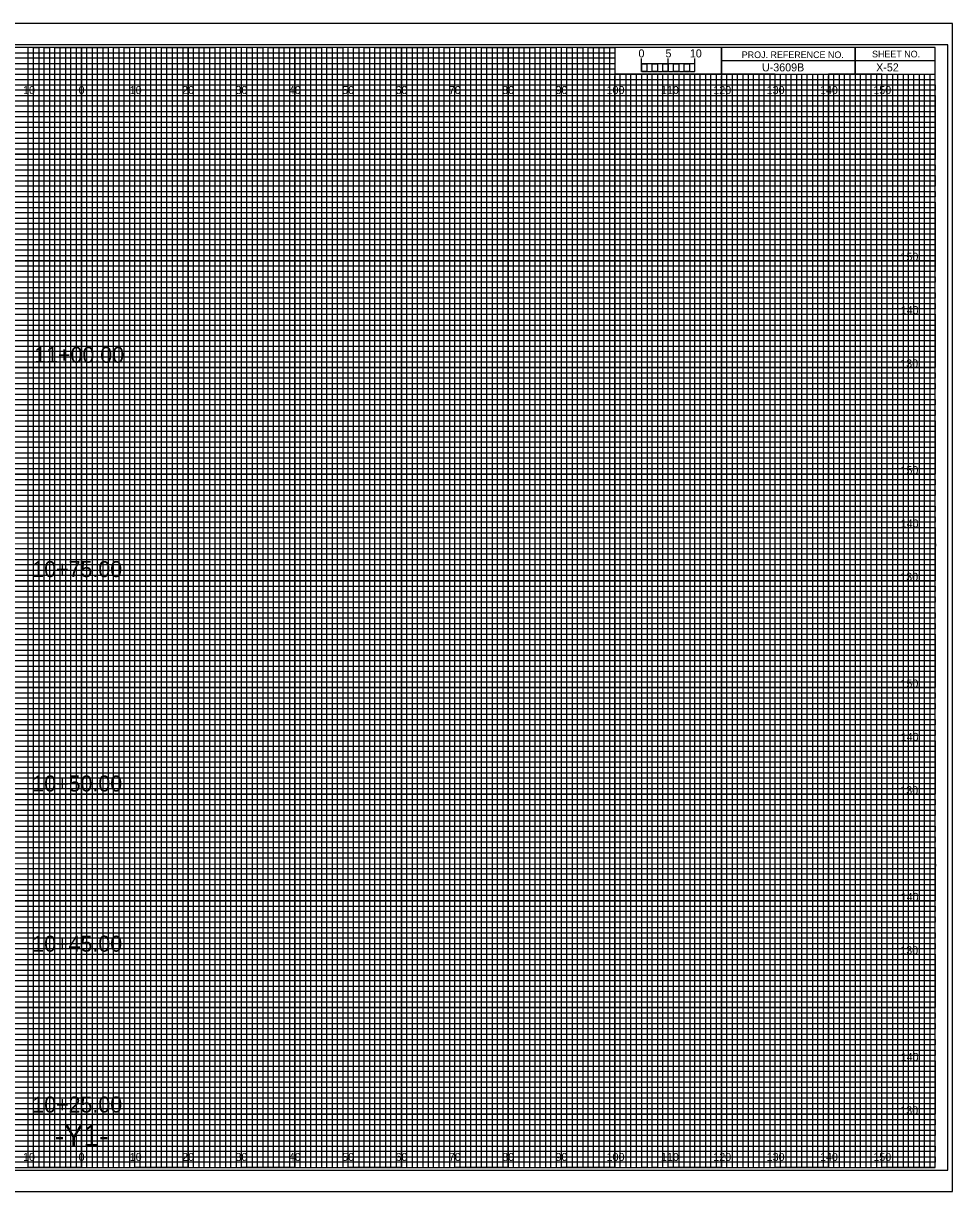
# Model space of a CAD drawing. Extents: x -13 to 323, y -5 to 2634.
# Drawn here: x 149.1 to 323.3, y -4.5 to 214.5 of the extents above; entities that cross this region are included whole.
import ezdxf

# ---------------------------------------------------------------- set-up
doc = ezdxf.new("R2010")
doc.units = 0
for name, color, linetype in [('Exist Cross Section Cell', 7, 'Continuous'), ('Exist XS Center Line Elevation Label', 7, 'Continuous'), ('Exist XS Ground Line', 7, 'Continuous'), ('Prop CMT Pvmt Course 1', 7, 'Continuous'), ('Prop CMT Pvmt Course 1 Wedge', 7, 'Continuous'), ('Prop CMT Pvmt Course 2', 7, 'Continuous'), ('Prop CMT Pvmt Course 2 Wedge', 7, 'Continuous'), ('Prop CMT Pvmt Course 3', 7, 'Continuous'), ('Prop CMT Pvmt Course 3 Wedge', 7, 'Continuous'), ('Prop CMT Pvmt Surface Shoulder', 7, 'Continuous'), ('Prop CMT Pvmt Wedge Surface 3', 7, 'Continuous'), ('Prop CMT Shld Paved Course 1', 7, 'Continuous'), ('Prop CMT Shld Paved Course 2', 7, 'Continuous'), ('Prop CMT Shld Paved Course 3', 7, 'Continuous'), ('Prop CMT Slope Grass', 7, 'Continuous'), ('Prop CMT Subgrade Earthwork', 7, 'Continuous'), ('Scratch_Level_0', 7, 'Continuous')]:
    doc.layers.add(name, color=color, linetype=linetype)

msp = doc.modelspace()

# ---------------------------------------------------------------- linework, layer by layer
at = {"layer": 'Exist XS Center Line Elevation Label'}
for points in [[(145, 0), (155, 0), (155, 210), (165, 210), (165, 0), (175, 0), (175, 210), (185, 210), (185, 0), (195, 0), (195, 210), (205, 210), (205, 0), (215, 0), (215, 210), (225, 210), (225, 0), (235, 0), (235, 210), (245, 210), (245, 0), (255, 0), (255, 210), (259.93, 210), (260, 210), (260, 205), (264.99, 205), (264.99, 0), (275, 0), (275, 205), (285, 205), (285, 0), (295, 0), (295, 205), (305, 205), (305, 0), (315, 0), (315, 205)], [(0, 205), (275, 205)], [(0, 185), (320, 185), (320, 195), (0, 195)], [(0, 165), (320, 165), (320, 175), (0, 175)], [(0, 145), (320, 145), (320, 155), (0, 155)], [(0, 125), (320, 125), (320, 135), (0, 135)], [(0, 105), (320, 105), (320, 115), (0, 115)], [(0, 85), (320, 85), (320, 95), (0, 95)], [(0, 65), (320, 65), (320, 75), (0, 75)], [(0, 45), (320, 45), (320, 55), (0, 55)], [(0, 25), (320, 25), (320, 35), (0, 35)], [(0, 5), (320, 5), (320, 15), (0, 15)]]:
    msp.add_lwpolyline(points, dxfattribs=at)
at = {"layer": 'Exist XS Ground Line'}
for p, q in [((150, 210), (140, 210)), ((150, 0), (150, 210)), ((170, 210), (160, 210)), ((160, 210), (160, 0)), ((170, 0), (170, 210)), ((190, 210), (180, 210)), ((180, 210), (180, 0)), ((190, 0), (190, 210)), ((210, 210), (200, 210)), ((200, 210), (200, 0)), ((210, 0), (210, 210)), ((230, 210), (220, 210)), ((220, 210), (220, 0)), ((230, 0), (230, 210)), ((250, 210), (240, 210)), ((240, 210), (240, 0)), ((250, 0), (250, 210)), ((260, 210), (260, 0)), ((270, 0), (270, 205)), ((290, 205), (280, 205)), ((280, 205), (280, 0)), ((290, 0), (290, 205)), ((310, 205), (300, 205)), ((300, 205), (300, 0)), ((310, 0), (310, 205)), ((160, 0), (150, 0)), ((180, 0), (170, 0)), ((200, 0), (190, 0)), ((220, 0), (210, 0)), ((240, 0), (230, 0)), ((260, 0), (250, 0)), ((280, 0), (270, 0)), ((300, 0), (290, 0)), ((320, 0), (310, 0)), ((320, 0), (320, 0))]:
    msp.add_line(p, q, dxfattribs=at)
for points in [[(0, 200), (320, 200), (320, 190), (0, 190)], [(0, 180), (320, 180), (320, 170), (0, 170)], [(0, 160), (320, 160), (320, 150), (0, 150)], [(0, 140), (320, 140), (320, 130), (0, 130)], [(0, 120), (320, 120), (320, 110), (0, 110)], [(0, 100), (320, 100), (320, 90), (0, 90)], [(0, 80), (320, 80), (320, 70), (0, 70)], [(0, 60), (320, 60), (320, 50), (0, 50)], [(0, 40), (320, 40), (320, 30), (0, 30)], [(0, 20), (320, 20), (320, 10), (0, 10)]]:
    msp.add_lwpolyline(points, dxfattribs=at)
at = {"layer": 'Prop CMT Pvmt Course 1'}
for p, q in [((265, 205.49), (265, 207.9)), ((265, 206.9), (265, 207.9)), ((270, 205.49), (270, 207.9)), ((275, 205.49), (275, 207.9)), ((275, 206.9), (275, 207.9))]:
    msp.add_line(p, q, dxfattribs=at)
for points in [[(275, 206.9), (265, 206.9), (265, 205.49), (275, 205.49)], [(265, 206.9), (266, 206.9), (266, 205.49), (265, 205.49)], [(267, 206.9), (268, 206.9), (268, 205.49), (267, 205.49)], [(269, 206.9), (270, 206.9), (270, 205.49), (269, 205.49)], [(271, 206.9), (272, 206.9), (272, 205.49), (271, 205.49)], [(273, 206.9), (274, 206.9), (274, 205.49), (273, 205.49)]]:
    msp.add_lwpolyline(points, close=True, dxfattribs=at)
at = {"layer": 'Prop CMT Pvmt Surface Shoulder'}
for p, q in [((267, 205), (266.01, 205)), ((266.01, 205), (266.01, 0)), ((267, 0), (267, 205)), ((269, 205), (268, 205)), ((268, 205), (268, 0)), ((269, 0), (269, 205)), ((266.01, 0), (265, 0)), ((268, 0), (267, 0))]:
    msp.add_line(p, q, dxfattribs=at)
for points in [[(150, 0), (151, 0), (151, 210), (152, 210), (152, 0)], [(152, 0), (153, 0), (153, 210), (154, 210), (154, 0)], [(155, 0), (156, 0), (156, 210), (157, 210), (157, 0)], [(157, 0), (158, 0), (158, 210), (159, 210), (159, 0)], [(160, 0), (161, 0), (161, 210), (162, 210), (162, 0)], [(162, 0), (163, 0), (163, 210), (164, 210), (164, 0)], [(165, 0), (166, 0), (166, 210), (167, 210), (167, 0)], [(167, 0), (168, 0), (168, 210), (169, 210), (169, 0)], [(170, 0), (171, 0), (171, 210), (172, 210), (172, 0)], [(172, 0), (173, 0), (173, 210), (174, 210), (174, 0)], [(175, 0), (176, 0), (176, 210), (177, 210), (177, 0)], [(177, 0), (178, 0), (178, 210), (179, 210), (179, 0)], [(180, 0), (181, 0), (181, 210), (182, 210), (182, 0)], [(182, 0), (183, 0), (183, 210), (184, 210), (184, 0)], [(185, 0), (186, 0), (186, 210), (187, 210), (187, 0)], [(187, 0), (188, 0), (188, 210), (189, 210), (189, 0)], [(190, 0), (191, 0), (191, 210), (192, 210), (192, 0)], [(192, 0), (193, 0), (193, 210), (194, 210), (194, 0)], [(195, 0), (196, 0), (196, 210), (197, 210), (197, 0)], [(197, 0), (198, 0), (198, 210), (199, 210), (199, 0)], [(200, 0), (201, 0), (201, 210), (202, 210), (202, 0)], [(202, 0), (203, 0), (203, 210), (204, 210), (204, 0)], [(205, 0), (206, 0), (206, 210), (207, 210), (207, 0)], [(207, 0), (208, 0), (208, 210), (209, 210), (209, 0)], [(210, 0), (211, 0), (211, 210), (212, 210), (212, 0)], [(212, 0), (213, 0), (213, 210), (214, 210), (214, 0)], [(215, 0), (216, 0), (216, 210), (217, 210), (217, 0)], [(217, 0), (218, 0), (218, 210), (219, 210), (219, 0)], [(220, 0), (221, 0), (221, 210), (222, 210), (222, 0)], [(222, 0), (223, 0), (223, 210), (224, 210), (224, 0)], [(225, 0), (226, 0), (226, 210), (227, 210), (227, 0)], [(227, 0), (228, 0), (228, 210), (229, 210), (229, 0)], [(230, 0), (231, 0), (231, 210), (232, 210), (232, 0)], [(232, 0), (233, 0), (233, 210), (234, 210), (234, 0)], [(235, 0), (236, 0), (236, 210), (237, 210), (237, 0)], [(237, 0), (238, 0), (238, 210), (239, 210), (239, 0)], [(240, 0), (241, 0), (241, 210), (242, 210), (242, 0)], [(242, 0), (243, 0), (243, 210), (244, 210), (244, 0)], [(245, 0), (246, 0), (246, 210), (247, 210), (247, 0)], [(247, 0), (248, 0), (248, 210), (249, 210), (249, 0)], [(250, 0), (251, 0), (251, 210), (252, 210), (252, 0)], [(252, 0), (253, 0), (253, 210), (254, 210), (254, 0)], [(255, 0), (256, 0), (256, 210), (257, 210), (257, 0)], [(257, 0), (258, 0), (258, 210), (259, 210), (259, 0)], [(260, 0), (261, 0), (261, 205), (262.02, 205), (262.02, 0)], [(262, 0), (263, 0), (263, 205), (263.99, 205), (263.99, 0)], [(270, 0), (270.98, 0), (270.98, 205), (272, 205), (272, 0)], [(272, 0), (273, 0), (273, 205), (274.05, 205), (274.05, 0)], [(275, 0), (276, 0), (276, 205), (277, 205), (277, 0)], [(277, 0), (278, 0), (278, 205), (279, 205), (279, 0)], [(280, 0), (281, 0), (281, 205), (282, 205), (282, 0)], [(282, 0), (283, 0), (283, 205), (284, 205), (284, 0)], [(285, 0), (286, 0), (286, 205), (287, 205), (287, 0)], [(287, 0), (288, 0), (288, 205), (289, 205), (289, 0)], [(290, 0), (291, 0), (291, 205), (292, 205), (292, 0)], [(292, 0), (293, 0), (293, 205), (294, 205), (294, 0)], [(295, 0), (296, 0), (296, 205), (297, 205), (297, 0)], [(297, 0), (298, 0), (298, 205), (299, 205), (299, 0)], [(300, 0), (301, 0), (301, 205), (302, 205), (302, 0)], [(302, 0), (303, 0), (303, 205), (304, 205), (304, 0)], [(305, 0), (306, 0), (306, 205), (307, 205), (307, 0)], [(307, 0), (308, 0), (308, 205), (309, 205), (309, 0)], [(310, 0), (311, 0), (311, 205), (312, 205), (312, 0)], [(312, 0), (313, 0), (313, 205), (314, 205), (314, 0)], [(315, 0), (316, 0), (316, 205), (317, 205), (317, 0)], [(317, 0), (318, 0), (318, 205), (319, 205), (319, 0)]]:
    msp.add_lwpolyline(points, dxfattribs=at)
at = {"layer": 'Prop CMT Pvmt Wedge Surface 3'}
for p, q in [((305, 210), (305, 205)), ((305, 205), (305, 210)), ((280, 207.5), (280, 205)), ((320, 207.49), (280, 207.49)), ((280, 205), (320, 205))]:
    msp.add_line(p, q, dxfattribs=at)
for points in [[(320, 210), (0, 210), (0, 0), (320, 0)], [(280, 210), (260, 210), (260, 205.03), (280, 205.03)], [(320, 210), (280, 210), (280, 205), (320, 205)]]:
    msp.add_lwpolyline(points, close=True, dxfattribs=at)
at = {"layer": 'Prop CMT Shld Paved Course 1'}
for p, q in [((150, 0), (150, 210)), ((160, 0), (160, 210)), ((170, 0), (170, 210)), ((180, 0), (180, 210)), ((190, 0), (190, 210)), ((200, 0), (200, 210)), ((210, 0), (210, 210)), ((220, 0), (220, 210)), ((230, 0), (230, 210)), ((240, 0), (240, 210)), ((250, 0), (250, 210)), ((260, 0), (260, 204.69)), ((270, 0), (270, 204.69)), ((280, 0), (280, 204.69)), ((290, 0), (290, 204.69)), ((300, 0), (300, 204.69)), ((310, 0), (310, 204.69)), ((0, 200), (320, 200)), ((0, 190), (320, 190)), ((0, 180), (320, 180)), ((0, 170), (320, 170)), ((0, 160), (320, 160)), ((0, 150), (320, 150)), ((0, 140), (320, 140)), ((0, 130), (320, 130)), ((0, 120), (320, 120)), ((0, 110), (320, 110)), ((0, 100), (320, 100)), ((0, 90), (320, 90)), ((0, 80), (320, 80)), ((0, 70), (320, 70)), ((0, 60), (320, 60)), ((0, 50), (320, 50)), ((0, 40), (320, 40)), ((0, 30), (320, 30)), ((0, 20), (320, 20)), ((0, 10), (320, 10))]:
    msp.add_line(p, q, dxfattribs=at)
at = {"layer": 'Prop CMT Shld Paved Course 2'}
for p, q in [((323.3, 214.5), (-13.4, 214.5)), ((-13.4, -4.5), (323.3, -4.5))]:
    msp.add_line(p, q, dxfattribs=at)
at = {"layer": 'Prop CMT Slope Grass'}
msp.add_lwpolyline([(-10.8, -0.5), (322.4, -0.5), (322.4, 210.5), (-10.8, 210.5)], close=True, dxfattribs=at)
at = {"layer": 'Prop CMT Subgrade Earthwork'}
msp.add_lwpolyline([(-13.4, -4.5), (323.3, -4.5), (323.3, 214.5), (-13.4, 214.5)], close=True, dxfattribs=at)
at = {"layer": 'Scratch_Level_0'}
for p, q in [((0, 209), (260, 209)), ((260, 209), (260, 207.98)), ((260, 207.98), (0, 207.98)), ((0, 207), (260, 207)), ((260, 205.89), (0, 205.89)), ((260, 207), (260, 205.89)), ((0, 204), (320, 204))]:
    msp.add_line(p, q, dxfattribs=at)
for points in [[(0, 203), (270, 203), (320, 203), (320, 202), (0, 202)], [(0, 201), (320, 201), (320, 199), (0, 199)], [(0, 198), (320, 198), (320, 197), (0, 196.98)], [(0, 196), (320, 196), (320, 194), (0, 194)], [(0, 193), (320, 193), (320, 192), (0, 192)], [(0, 191), (320, 191), (320, 189), (0, 189)], [(0, 188), (320, 188), (320, 187), (0, 187)], [(0, 186), (320, 186), (320, 184), (0, 184)], [(0, 183), (320, 183), (320, 182), (0, 182)], [(0, 181), (320, 181), (320, 179), (0, 179)], [(0, 178), (320, 178), (320, 177), (0, 177)], [(0, 176), (320, 176), (320, 173.95), (320, 173), (320, 172), (0, 172)], [(0, 174), (320, 174), (320, 173), (0, 173)], [(0, 171), (320, 171), (320, 169), (0, 169.03)], [(0, 169.03), (320, 169), (320, 168), (0, 168)], [(0, 167), (320, 167), (320, 166), (0, 166)], [(0, 164), (320, 164), (320, 163), (0, 163)], [(0, 162), (320, 162), (320, 161), (0, 161)], [(-0.07, 158.89), (320, 158.89), (320, 157.88), (-0.07, 157.88)], [(0, 157), (320, 157), (320, 156), (0, 156)], [(0, 154), (320, 154), (320, 153), (0, 153)], [(0, 152), (320, 152), (320, 151), (0, 151)], [(0, 149), (320, 149), (320, 148), (0, 148)], [(0, 147), (320, 147), (320, 146), (0, 146)], [(0, 144), (320, 144), (320, 143), (0, 143)], [(0, 142), (320, 142), (320, 141), (0, 141)], [(0, 139), (320, 139), (319.99, 137.98), (0, 138)], [(0, 137), (320, 137), (320, 136), (0, 136)], [(0, 134), (320, 134), (320, 133), (0, 133)], [(0, 132), (320, 132), (320, 131), (0, 131)], [(0, 129), (320, 129), (320, 128), (0, 128)], [(0, 127), (320, 127), (320, 126), (0, 126)], [(0, 124), (320, 124), (320, 123), (0, 123)], [(0, 122), (320, 122), (320, 121), (0, 121)], [(0, 119), (320, 119), (320, 118), (0, 118)], [(0, 116.99), (320.07, 116.91), (320, 116), (0, 116)], [(0, 114), (320, 114), (320, 113), (0, 113)], [(0, 112), (320, 112), (320, 111), (0, 111)], [(0, 109), (320, 109), (320, 108), (0, 108)], [(0, 107), (320, 107), (320, 106), (0, 106)], [(0, 104), (320, 104), (320, 103), (0, 103)], [(0, 102), (320, 102), (320, 101), (0, 101)], [(0, 99), (320, 99), (320, 98), (0, 98)], [(0, 97), (320, 97), (320, 96), (0, 96)], [(0, 94), (320, 94), (320, 93), (0, 93)], [(0, 92), (320, 92), (320, 91), (0, 91)], [(0, 89), (320, 89), (320, 88), (0, 88)], [(0, 87), (320, 87), (320, 86), (0, 86)], [(0, 84), (320, 84), (320, 83), (0, 83)], [(0, 82), (320, 82), (320, 81), (0, 81)], [(0, 79), (320, 79), (319.99, 77.98), (0, 78)], [(0, 77), (320, 77), (320, 76), (0, 76)], [(0, 74), (320, 74), (320, 73), (0, 73)], [(0, 72), (320, 72), (320, 71), (0, 71)], [(0, 69), (320, 69), (320, 68), (0, 68)], [(0, 67), (320, 67), (320, 66), (0, 66)], [(0, 64), (320, 64), (320, 63), (0, 63)], [(0, 62), (320, 62), (320, 61), (0, 61)], [(0, 59), (320, 59), (320, 58), (0, 58)], [(0, 56.99), (320.07, 56.91), (320, 56), (0, 56)], [(0, 54), (320, 54), (320, 53), (0, 53)], [(0, 52), (320, 52), (320, 51), (0, 51)], [(0, 49), (320, 49), (320, 48), (0, 48)], [(0, 47), (320, 47), (320, 46), (0, 46)], [(0, 44), (320, 44), (320, 43), (0, 43)], [(0, 42), (320, 42), (320, 41), (0, 41)], [(0, 39), (320, 39), (320, 38), (0, 38)], [(0, 37), (320, 37), (320, 36), (0, 36)], [(0, 34), (320, 34), (320, 33), (0, 33)], [(0, 32), (320, 32), (320, 31), (0, 31)], [(0, 29), (320, 29), (320, 28), (0, 28)], [(0, 27), (320, 27), (320, 26), (0, 26)], [(0, 24), (320, 24), (320, 23), (0, 23)], [(0, 22), (320, 22), (320, 21), (0, 21)], [(0, 19), (320, 19), (320, 18), (0, 18)], [(0, 17), (320, 17), (320, 16), (0, 16)], [(0, 14), (320, 14), (320, 13), (0, 13)], [(0, 12), (320, 12), (320, 11), (0, 11)], [(0, 9), (320, 9), (320, 8), (0, 8)], [(0, 7), (320, 7), (320, 6), (0, 6)], [(0, 4), (320, 4), (320, 3), (0, 3)], [(0, 2), (320, 2), (320, 1), (0, 1)]]:
    msp.add_lwpolyline(points, dxfattribs=at)

# ---------------------------------------------------------------- texts
at = {"layer": 'Exist Cross Section Cell'}
for s, p in [('10', (149.04, 201.25)), ('0', (159.45, 201.25)), ('0', (159.45, 201.25)), ('10', (169.04, 201.25)), ('20', (178.86, 201.25)), ('30', (188.86, 201.25)), ('40', (198.86, 201.25)), ('50', (208.86, 201.25)), ('60', (218.86, 201.25)), ('70', (228.86, 201.25)), ('80', (238.86, 201.25)), ('90', (248.86, 201.25)), ('100', (258.44, 201.25)), ('110', (268.62, 201.25)), ('120', (278.44, 201.25)), ('130', (288.44, 201.25)), ('140', (298.44, 201.25)), ('150', (308.44, 201.25)), ('10', (149.04, 1.25)), ('0', (159.45, 1.25)), ('0', (159.45, 1.25)), ('10', (169.04, 1.25)), ('20', (178.86, 1.25)), ('30', (188.86, 1.25)), ('40', (198.86, 1.25)), ('50', (208.86, 1.25)), ('60', (218.86, 1.25)), ('70', (228.86, 1.25)), ('80', (238.86, 1.25)), ('90', (248.86, 1.25)), ('100', (258.44, 1.25)), ('110', (268.62, 1.25)), ('120', (278.44, 1.25)), ('130', (288.44, 1.25)), ('140', (298.44, 1.25)), ('150', (308.44, 1.25))]:
    msp.add_text(s, height=1.5, dxfattribs=at).set_placement(p)
at = {"layer": 'Prop CMT Pvmt Course 1'}
msp.add_text('0', height=1.5, dxfattribs=at).set_placement((264.41, 208.12))
at = {"layer": 'Prop CMT Pvmt Course 1 Wedge'}
msp.add_text('U-3609B', height=1.5, dxfattribs=at).set_placement((287.56, 205.5))
at = {"layer": 'Prop CMT Pvmt Course 2'}
for s, p in [('11+00.00', (151.13, 150.87)), ('10+75.00', (150.77, 110.7)), ('10+50.00', (150.77, 70.51)), ('10+45.00', (150.77, 40.48)), ('10+25.00', (150.77, 10.33))]:
    msp.add_text(s, height=3, dxfattribs=at).set_placement(p)
at = {"layer": 'Prop CMT Pvmt Course 2 Wedge'}
msp.add_text('-Y1-', height=4, dxfattribs=at).set_placement((154.99, 4))
at = {"layer": 'Prop CMT Pvmt Course 3'}
msp.add_text('X-52', height=1.5, dxfattribs=at).set_placement((308.96, 205.5))
at = {"layer": 'Prop CMT Pvmt Course 3 Wedge'}
for s, p in [('5', (269.47, 208.12)), ('10', (274.04, 208.12))]:
    msp.add_text(s, height=1.5, dxfattribs=at).set_placement(p)
at = {"layer": 'Prop CMT Pvmt Wedge Surface 3'}
for s, p in [('PROJ. REFERENCE NO.', (283.77, 207.99)), ('SHEET NO.', (308.19, 208.12))]:
    msp.add_text(s, height=1.25, dxfattribs=at).set_placement(p)
at = {"layer": 'Prop CMT Shld Paved Course 3'}
for s, p in [('150', (313.52, 170)), ('140', (313.57, 160)), ('130', (313.49, 150)), ('150', (313.52, 130)), ('140', (313.57, 120)), ('130', (313.49, 110)), ('150', (313.52, 90)), ('140', (313.57, 80)), ('130', (313.49, 70)), ('140', (313.57, 50)), ('130', (313.49, 40)), ('140', (313.57, 20)), ('130', (313.49, 10))]:
    msp.add_text(s, height=1.5, dxfattribs=at).set_placement(p)

doc.saveas('drawing.dxf')
